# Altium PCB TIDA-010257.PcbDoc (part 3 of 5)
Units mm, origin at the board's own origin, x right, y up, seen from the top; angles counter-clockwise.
Board outline 250 x 270 mm, 2 copper layers (Top Layer, Bottom Layer), stack 1.575 mm thick; 458 components, 220 nets, 1154 pads, 1226 vias.
Unrouted connection lines stored in the file: 314.
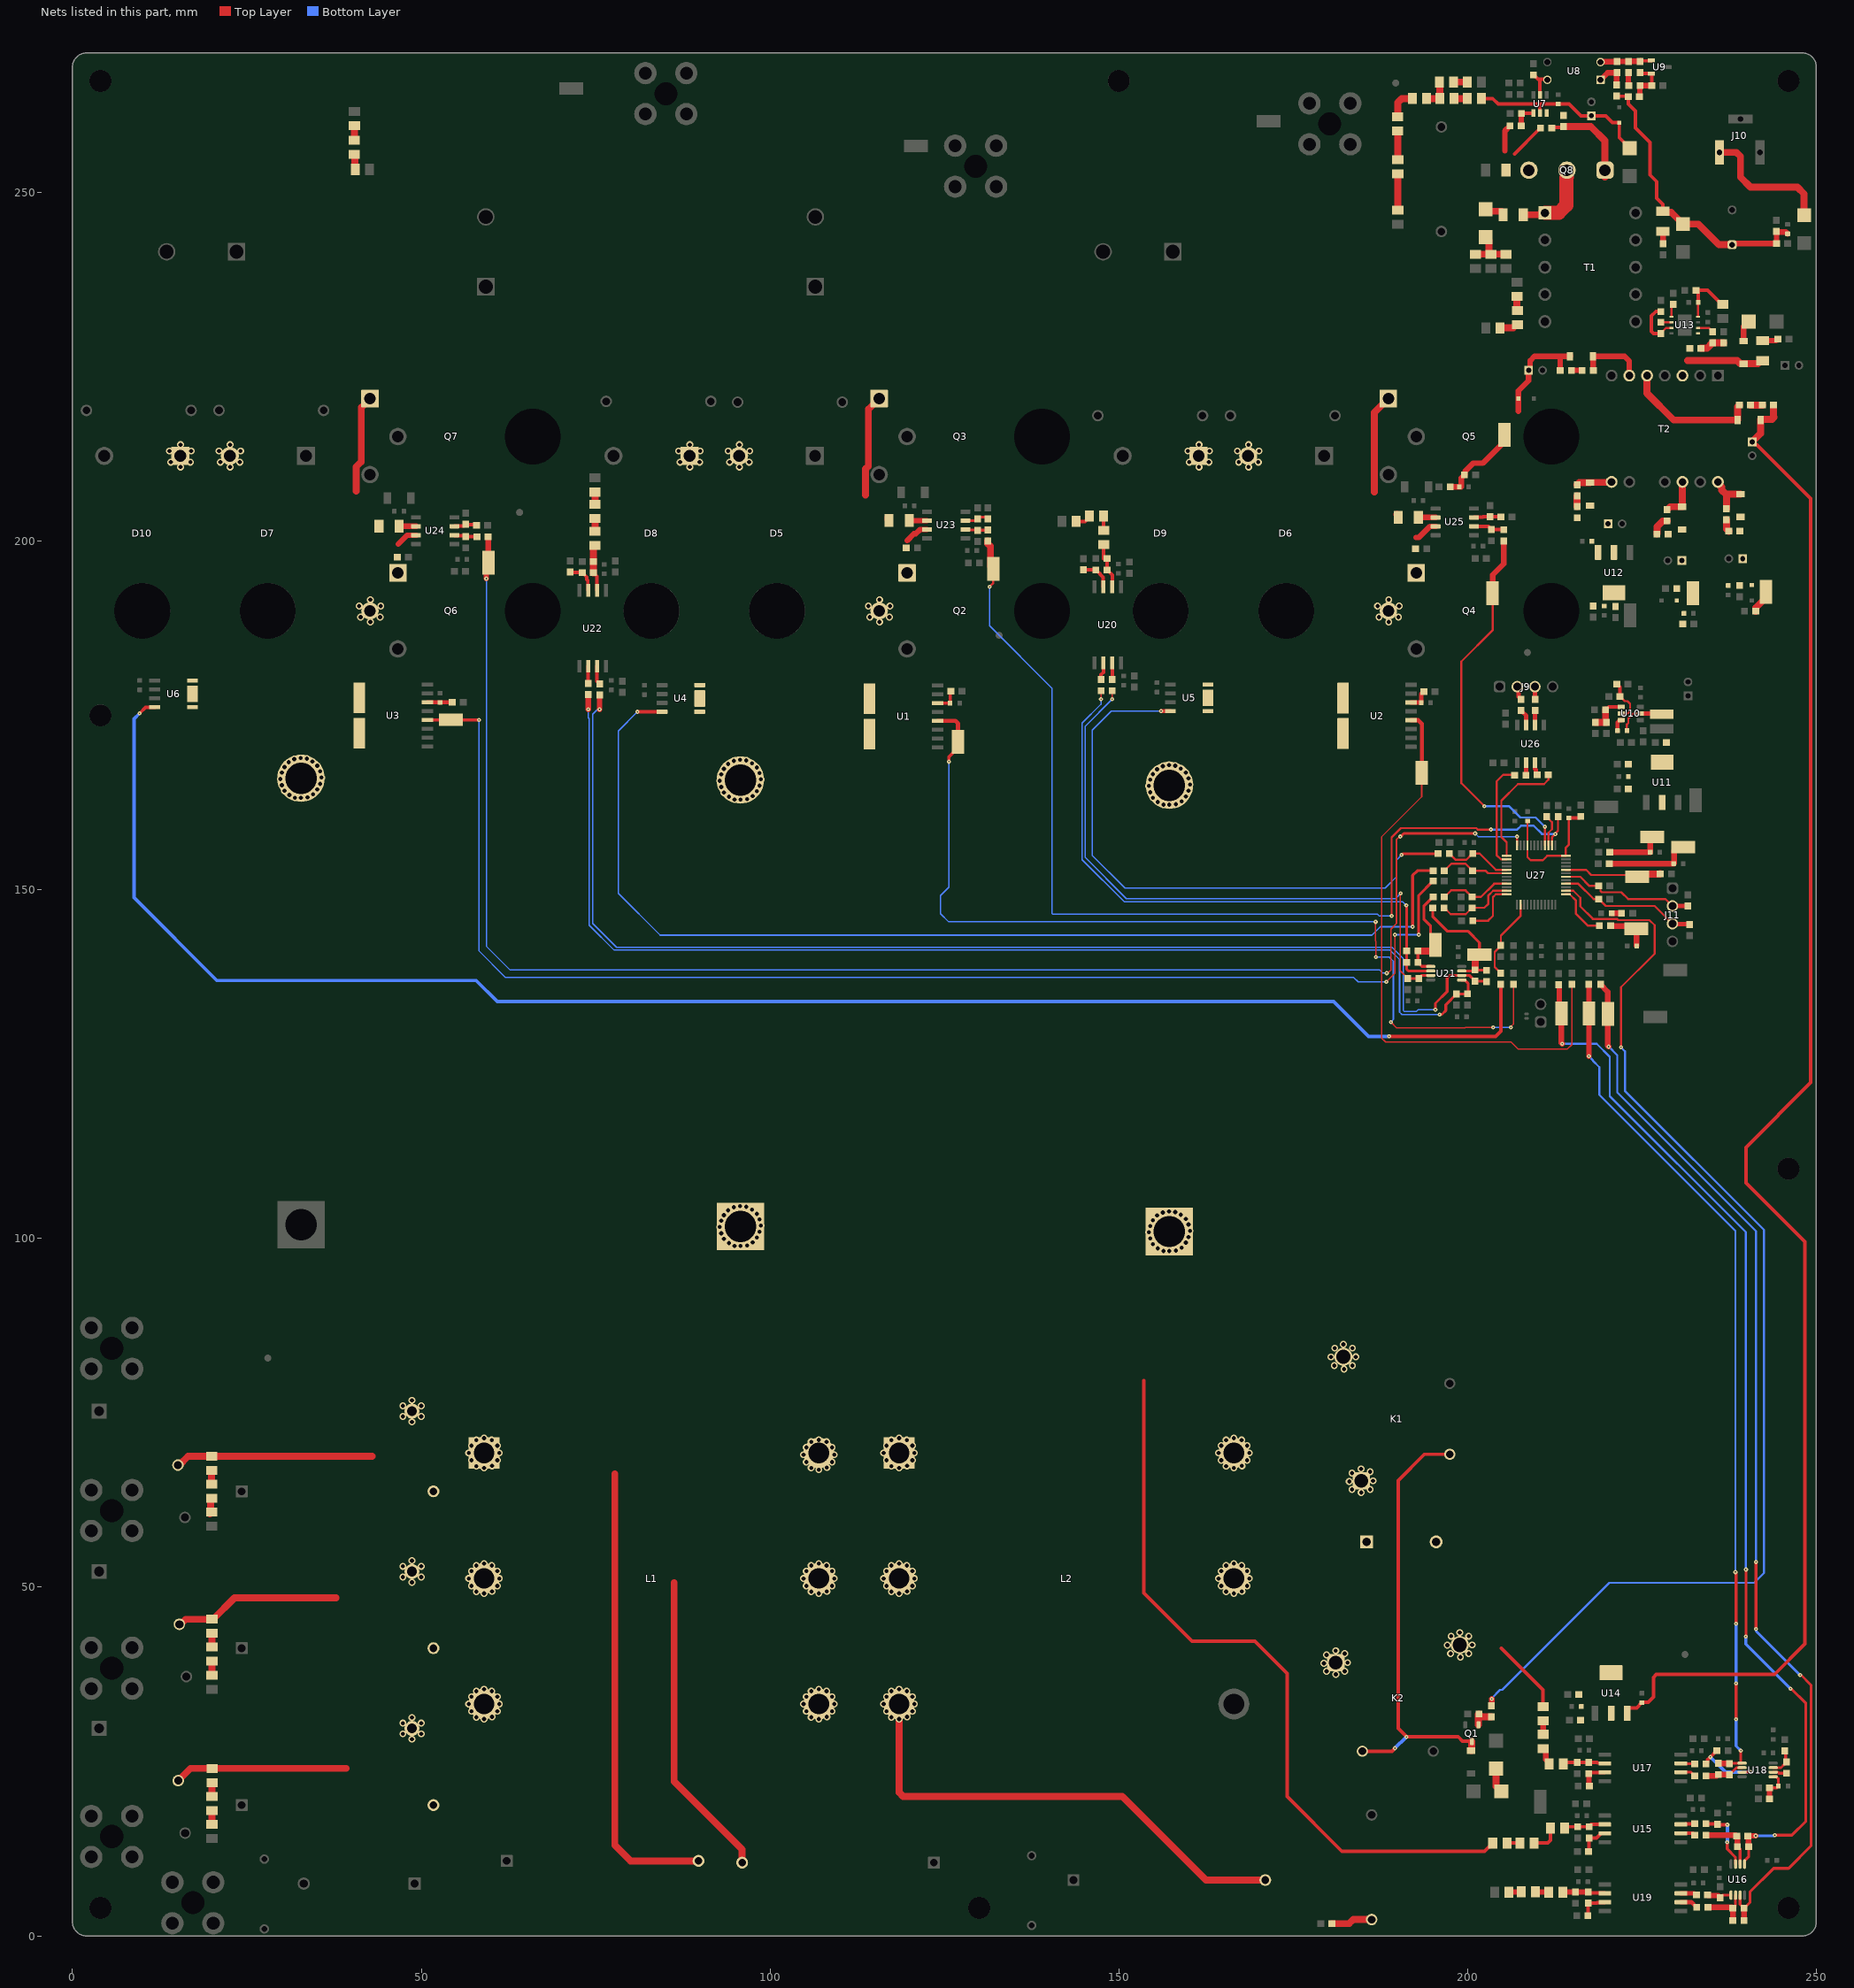
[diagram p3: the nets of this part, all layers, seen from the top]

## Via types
v1: diameter 1, hole 0.6, Top Layer to Bottom Layer, 760 vias
v2: diameter 0.6, hole 0.2, Top Layer to Bottom Layer, 452 vias
v3: diameter 1.27, hole 0.711, Top Layer to Bottom Layer, 10 vias
v4: diameter 0.5, hole 0.2, Top Layer to Bottom Layer, 4 vias

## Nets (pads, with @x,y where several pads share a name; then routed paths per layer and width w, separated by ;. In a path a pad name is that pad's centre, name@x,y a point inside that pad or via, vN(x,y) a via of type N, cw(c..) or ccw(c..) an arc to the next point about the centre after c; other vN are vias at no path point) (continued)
MCU_TCK: C151.1 J11.3 R153.1 U27.28 | length 20.3
  Top Layer w0.3: U27.28@214.088,150.877 215.878,150.877 218.07,148.685 218.467,148.685 C151.1@218.792,148.36 ; C151.1@218.792,148.684 218.817,148.684 219.815,147.686 226.824,147.686 J11.3@229.364,145.146
  Top Layer w0.6: J11.3@229.364,145.146 229.415,145.095 231.776,145.095 R153.1@231.826,145.045
MCU_TMS: C150.1 J11.2 R152.1 U27.30 | length 19.5
  Top Layer w0.3: U27.30@214.088,151.877 216.167,151.877 217.485,150.559 C150.1@218.805,150.559 219.05,150.314 219.05,149.835 219.226,149.659 222.053,149.659 223.04,148.673 228.378,148.673 J11.2@229.364,147.686
  Top Layer w0.6: J11.2@229.364,147.686 R152.1@231.601,147.686
NetC1_2: C1.2 F3.2 L1.5 R5.2 RV2.2 | length 24.8
  Top Layer w1: RV2.2@15.15,22.25 16.916,24.016 R5.2@20,24.016 39.25,24.016
  other v1: 48.67,28.2 47.36,28.968 50,28.968 47.36,30.5 50,30.5 59,31.1 48.67,31.3 57.9,31.35 60.15,31.4 57.2,32.2 60.9,32.2 56.8,33.25 61.2,33.25 57.2,34.3 60.9,34.3 57.9,35.1 60.1,35.1 59,35.375
NetC2_2: C2.2 F2.2 L1.3 R4.2 RV3.2 | length 24
  Top Layer w1: RV3.2@15.325,44.687 15.501,44.687 16.214,45.4 R4.2@19.991,45.4 20.157,45.4 23.225,48.469 37.781,48.469
  other v1: 59,49.1 57.9,49.35 60.15,49.4 57.2,50.2 60.9,50.2 48.67,50.7 56.8,51.25 61.2,51.25 47.36,51.468 50,51.468 57.2,52.3 60.9,52.3 47.36,53 50,53 57.9,53.1 60.1,53.1 59,53.375 48.67,53.8
NetC3_2: C3.2 F1.2 L1.1 R3.2 RV1.2 | length 28.4
  Top Layer w1: RV1.2@15.117,67.5 15.293,67.5 16.543,68.75 R3.2@19.95,68.75 42.95,68.75
  other v1: 59,67.1 57.9,67.35 60.15,67.4 57.2,68.2 60.9,68.2 56.8,69.25 61.2,69.25 57.2,70.3 60.9,70.3 57.9,71.1 60.1,71.1 59,71.375 48.67,73.7 47.36,74.468 50,74.468 47.36,76 50,76 48.67,76.8
NetC4_2: C4.2 L1.4 L2.3 | length 44.2
  Top Layer w1: 86.25,50.664 86.25,22.15 96,12.4 C4.2@96,10.5
  other v1: 107,49.1 118.5,49.1 105.9,49.35 117.4,49.35 108.15,49.4 119.65,49.4 105.2,50.2 108.9,50.2 116.7,50.2 120.4,50.2 104.8,51.25 109.2,51.25 116.3,51.25 120.7,51.25 105.2,52.3 108.9,52.3 116.7,52.3 120.4,52.3 105.9,53.1 108.1,53.1 117.4,53.1 119.6,53.1 107,53.375 118.5,53.375
NetC5_2: C5.2 L1.2 L2.1 | length 66.2
  Top Layer w1: 77.75,66.25 77.75,13 80,10.75 C5.2@89.75,10.75
  other v1: 107,66.85 105.9,67.1 118.5,67.1 108.15,67.15 117.4,67.35 119.65,67.4 105.2,67.95 108.9,67.95 116.7,68.2 120.4,68.2 104.8,69 109.2,69 116.3,69.25 120.7,69.25 105.2,70.05 108.9,70.05 116.7,70.3 120.4,70.3 105.9,70.85 108.1,70.85 117.4,71.1 119.6,71.1 107,71.125 118.5,71.375
NetC6_2: C6.2 L1.6 L2.5 | length 70.4
  Top Layer w1: L2.5@118.5,33.25 118.5,20.586 119.086,20 150.5,20 162.5,8 C6.2@171,8
  other v1: 107,31.1 118.5,31.1 105.9,31.35 117.4,31.35 108.15,31.4 119.65,31.4 105.2,32.2 108.9,32.2 116.7,32.2 120.4,32.2 104.8,33.25 109.2,33.25 116.3,33.25 120.7,33.25 105.2,34.3 108.9,34.3 116.7,34.3 120.4,34.3 105.9,35.1 108.1,35.1 117.4,35.1 119.6,35.1 107,35.375 118.5,35.375
NetC10_1: C10.1 R12.1 | length 6
  Top Layer w1: R12.1@180.55,1.75 183.004,1.75 183.62,2.366 C10.1@186.25,2.366
NetC13_1: C13.1 L3.2 U1.8 | length 3.7
  Top Layer w0.4: U1.8@124.02,176.78 C13.1@125.825,176.78 125.825,178.184 126.12,178.479 L3.2@126.145,178.479
NetC20_1: C20.1 L6.2 U2.8 | length 3.2
  Top Layer w0.6: U2.8@191.899,176.862 C20.1@193.353,176.862 193.353,178.093 193.699,178.44 L6.2@193.724,178.44
NetC26_1: C26.1 L8.2 U3.8 | length 3.6
  Top Layer w0.4: L8.2@54.416,176.885 L8.2@54.436,176.905
  Top Layer w0.6: U3.8@50.875,176.905 52.618,176.905 52.658,176.865 C26.1@52.683,176.865 52.703,176.885 L8.2@54.416,176.885
NetC34_1: C34.1 R26.1 | length 1.8
  Top Layer w0.8: R26.1@227.999,244.421 228.028,244.392 228.028,242.698 C34.1@228.058,242.668
NetC35_1: C35.1 C36.2 D11.1 R25.2 R26.2 R28.2 R37.2 R45.2 | length 42.1
  Top Layer w0.5: R37.2@221.364,263.837 221.397,263.803 223.021,263.803 R45.2@223.055,263.77 223.055,262.679 224.057,261.676 224.057,259.29 226.144,257.203 226.144,252.514 227.098,251.56 227.098,249.173 227.999,248.271 R26.2@227.999,247.321
  Top Layer w0.8: C35.1@237.924,242.5 238.092,242.668 R25.2@244.294,242.668 244.289,242.673 R28.2@244.289,244.392 ; R28.2@244.284,244.421 244.289,244.417 R28.2@244.289,244.392 ; C36.2@245.885,244.075 245.639,244.321 244.359,244.321 R28.2@244.289,244.392
  Top Layer w1: R26.2@227.999,247.321 228.149,247.171 229.181,247.171 D11.1@230.872,245.48 233.074,245.48 236.053,242.5 C35.1@237.924,242.5
NetC38_2: C38.2 D12.1 R30.1 R31.1 | length 7.1
  Top Layer w1: R30.1@201.113,241.157 R31.1@203.192,241.157 ; D12.1@202.589,243.597 203.057,243.129 203.057,241.292 R31.1@203.192,241.157 ; C38.2@205.521,241.157 R31.1@203.357,241.157 R31.1@203.192,241.157
NetC39_1: C39.1 R46.1 | length 1.9
  Top Layer w0.5: C39.1@223.092,265.692 223.092,265.37 C39.1@223.135,265.328
  Top Layer w0.8: R46.1@223.05,267.207 223.05,265.734 C39.1@223.092,265.692
NetC39_2: C39.2 C42.1 R45.1 R49.2 U9.2 | length 6.6
  Top Layer w0.5: R45.1@224.655,263.77 R45.1@224.695,263.81 ; C42.1@224.75,267.207 224.876,267.08 226.295,267.08 226.395,266.98 R49.2@226.395,265.328
  Top Layer w0.8: R45.1@224.695,263.81 224.695,265.287 C39.2@224.735,265.328 R49.2@226.395,265.328
NetC40_2: C40.2 C41.1 D13.1 D14.1 R42.2 U7.5 | length 26.8
  Top Layer w0.5: R42.2@202.016,263.484 203.601,263.484 204.386,262.7 210.45,262.7 ; U7.5@210.386,261.4 210.386,262.636 210.45,262.7 ; D13.1@223.25,256.36 221.75,257.86 D14.1@221.75,260.007 220.779,260.007 219.786,261 C41.1@217.75,261 216.25,261 214.55,262.7 C40.2@213,262.7 210.45,262.7
NetC42_2: C42.2 R44.1 R46.2 U8.2 U9.1 | length 7.4
  Top Layer w0.5: C42.2@224.823,268.88 226.284,268.88 U9.1@226.334,268.93
  Top Layer w0.8: U8.2@219.06,268.706 219.097,268.743 221.364,268.743 R44.1@221.401,268.78 221.414,268.794 223.037,268.794 R46.2@223.05,268.807 C42.2@224.75,268.807 C42.2@224.823,268.88
NetC43_1: C43.1 R47.1 U7.4 | length 3.6
  Top Layer w0.5: C43.1@207.721,261.344 207.749,261.372 209.408,261.372 U7.4@209.436,261.4
  Top Layer w0.8: R47.1@207.685,259.545 207.703,259.563 207.703,261.326 C43.1@207.721,261.344
NetC45_2: C45.2 U7.2 U8.4 | length 4.5
  Top Layer w0.5: C45.2@209.46,266.853 209.46,266.828 209.685,266.603 209.71,266.603 210.09,266.223 210.45,266.223 ; U7.2@210.386,264 210.386,266.16 210.45,266.223 ; U8.4@211.44,266.166 211.382,266.223 210.45,266.223
NetC46_1: C46.1 L9.1 U10.2 | length 7.2
  Top Layer w0.3: C46.1@222.843,172.822 222.843,173.715 223.053,173.925 223.053,174.597 223.74,175.284 U10.2@224.776,175.284 ; C46.1@222.993,172.61 C46.1@222.993,172.822
  Top Layer w0.6: U10.2@224.776,175.284 227.743,175.284 L9.1@227.829,175.198
NetC46_2: C46.2 U10.6 | length 1.9
  Top Layer w0.6: C46.2@221.493,172.822 221.493,174.002 221.826,174.334 U10.6@222.026,174.334
NetC48_1: C48.1 C50.2 R51.1 R53.2 U11.2 U11.4
NetC49_1: C49.1 R54.1 R56.2 U10.4 | length 5.8
  Top Layer w0.5: R56.2@219.789,175.822 219.814,175.822 220.226,176.234 U10.4@222.026,176.234
  Top Layer w1: R54.1@218.341,174.026 219.789,174.026 C49.1@219.846,174.083 ; R56.2@219.789,175.822 219.789,174.141 C49.1@219.846,174.083 ; C49.1@219.903,174.026 C49.1@219.846,174.083
NetC53_1: C53.1 C56.2 R58.2 U12.2 U12.4
NetC54_1: C54.1 C55.2 D15.1 R59.2 U12.3
NetC57_1: C57.1 R59.1 | length 1.5
  Top Layer w1: R59.1@215.691,204.958 C57.1@215.691,206.475
NetC57_2: C57.2 D15.2 T2.8 | length 5.1
  Top Layer w1: C57.2@215.691,208.075 215.995,208.379 D15.2@217.557,208.379 ; D15.2@217.557,208.422 220.568,208.422 T2.8@220.646,208.5
NetC58_1: C58.1 R60.1 | length 2.8
  Top Layer w1: R60.1@227.147,201.032 227.186,201.071 227.186,202.088 228.004,202.907 C58.1@228.611,202.907
NetC58_2: C58.2 D16.2 T2.12 | length 5.9
  Top Layer w1: C58.2@228.611,204.507 229.036,204.933 D16.2@230.768,204.933 230.787,204.952 230.787,208.481 T2.12@230.806,208.5
NetC59_2: C59.2 C60.1 D16.1 D17.1 R60.2 R61.2 R62.2 TP10.1
NetC63_2: C63.2 R63.2 | length 2.3
  Top Layer w0.8: R63.2@242.281,228.756 244.242,228.756 244.469,228.983 C63.2@244.494,228.983
NetC64_2: C64.2 C66.1 D19.1 D21.1 R64.2 R65.2 R66.2 TP11.1 | length 3.4
  Top Layer w1: R64.2@241.3,189.941 241.3,190.423 242.806,191.929 TP11.1@242.806,192.755
NetC65_1: C65.1 R65.1 | length 1.8
  Top Layer w1: C65.1@237.127,203.065 237.127,201.753 R65.1@237.446,201.434
NetC65_2: C65.2 D19.2 T2.14 | length 6.5
  Top Layer w1: T2.14@235.886,208.5 235.886,208.311 236.44,207.758 236.44,207.327 237.025,206.742 ; C65.2@237.127,204.665 237.127,206.64 237.025,206.742 ; D19.2@239.135,206.742 237.025,206.742
NetC67_1: C67.1 R71.1 R72.2 | length 3.6
  Top Layer w1: R71.1@233.463,227.656 234.337,227.656 R72.2@235.115,228.433 236.697,228.433 C67.1@236.71,228.421
NetC68_2: C68.2 C70.1 D22.1 D23.1 R67.2 R69.2 R70.2 TP12.1 | length 28.6
  Top Layer w0.8: R67.2@197.514,207.807 C68.2@198.814,207.807 199.091,207.807 199.091,209.045 199.527,209.481 199.577,209.481 199.652,209.556 199.652,210.05 200.793,211.191 202.19,211.191 204.788,213.789 204.788,214.744 TP12.1@205.277,215.233 ; 207.297,218.625 D23.1@207.297,220.45 207.297,221.546 208.75,222.998 C70.1@208.75,224.5 208.975,224.725 208.975,225.886 209.589,226.5 213.227,226.5 ; R69.2@213.29,224.5 213.29,226.436 213.227,226.5 ; D22.1@214.631,226.71 214.688,226.653 D22.1@214.688,226.5 213.227,226.5
NetC69_1: C69.1 R69.1 | length 1.5
  Top Layer w0.8: R69.1@214.89,224.5 C69.1@216.415,224.5
NetC69_2: C69.2 D22.2 T2.6 | length 9.6
  Top Layer w0.8: C69.2@217.99,224.5 C69.2@218.015,224.5 217.989,224.526 217.989,226.474 D22.2@217.963,226.5 222.5,226.5 223.186,225.814 T2.6@223.186,223.74
NetC71_2: C71.2 R68.1 R76.2 U13.4 | length 8.6
  Top Layer w0.3: U13.4@233.04,232.183 233.045,232.183 233.045,234.232 C71.2@233.051,234.238
  Top Layer w0.5: R76.2@232.74,235.988 R76.2@232.765,235.988 ; C71.2@233.051,234.238 233.051,235.702 R76.2@232.765,235.988 ; R68.1@236.601,233.949 236.436,233.949 234.397,235.988 R76.2@232.765,235.988
NetC72_1: C72.1 U13.5 | length 1.9
  Top Layer w0.3: U13.5@229.24,232.183 229.24,233.712 C72.1@229.477,233.949
NetC73_1: C73.1 R78.1 | length 1.7
  Top Layer w1: C73.1@240.557,219.5 R78.1@242.254,219.5
NetC73_2: C73.2 D24.2 T2.5 | length 19.3
  Top Layer w1: T2.5@225.726,223.74 225.726,221.213 229.562,217.378 D24.2@238.73,217.378 238.73,219.273 C73.2@238.957,219.5
NetC74_1: C74.1 C77.2 R75.2 U14.2 U14.4
NetC75_1: C75.1 C76.2 D24.1 R78.2 U14.3 | length 222.5
  Top Layer w0.5: U14.3@222.879,31.928 222.879,32.475 223.104,32.7 224.227,32.7 224.975,33.448 C76.2@225,33.448 225.069,33.517 225.903,33.517 226.637,34.251 226.637,37.078 227.06,37.5 244.017,37.5 248.369,41.852 248.369,99.531 239.909,107.991 239.909,113.059 249.2,122.35 249.2,206.125 241.45,213.875 241.175,213.875 C75.1@240.8,214.25
  Top Layer w1: C75.1@240.8,214.25 242.005,215.456 D24.1@242.005,217.378 242.005,217.446 242.048,217.488 243.645,217.488 243.957,217.8 243.854,217.903 R78.2@243.854,219.5
NetC80_1: C80.1 R79.2 R85.2 TP14.1 U16.1 | length 151
  Top Layer w0.4: U16.1@239.712,10.292 239.712,10.755 240.287,11.33 C80.1@240.287,12.787 ; v2(239.9,42.912) 239.904,42.917 239.904,52.529 v2(239.909,52.533) ; v2(244.043,14.442) 246.505,14.442 248.5,16.437 248.5,33.342 246.397,35.445 246.392,35.44 v2(246.314,35.44)
  Top Layer w0.8: R85.2@213.088,136.396 213.163,136.321 213.163,132.555 TP14.1@213.453,132.265 213.453,128.041 v2(213.56,127.934) ; R79.2@240.182,14.334 240.192,14.344 v2(241.323,14.344) ; R79.2@240.282,14.259 240.282,14.234 240.287,14.229 C80.1@240.287,12.787
  Bottom Layer w0.3: v2(213.56,127.934) 218.517,127.934 220.392,126.059 220.392,120.427 239.909,100.91 v2(239.909,52.533)
  Bottom Layer w0.4: v2(239.9,42.912) 239.9,41.854 v2(246.314,35.44) ; v2(241.323,14.344) 243.933,14.344 244.03,14.442 v2(244.043,14.442)
NetC80_2: C80.2 R79.1 R84.2 U16.2 | length 12.2
  Top Layer w0.4: U16.2@239.062,10.292 C80.2@239.062,12.437
  Top Layer w0.5: R84.2@234.18,14.442 234.234,14.388 237.981,14.388 238.035,14.334 ; C80.2@238.881,12.618 C80.2@239.062,12.437
  Top Layer w0.8: R84.2@234.18,14.442 R79.1@238.449,14.442 ; R79.1@238.582,14.334 238.607,14.334 238.682,14.259 238.682,14.234 238.687,14.229 C80.2@238.687,12.787
NetC83_1: C83.1 R82.2 R83.2 U15.2 | length 6
  Top Layer w0.5: R82.2@213.911,15.458 214.099,15.646 R83.2@215.763,15.646 C83.1@217.426,15.646 217.426,15.671 217.736,15.981 U15.2@219.677,15.981
NetC83_2: C83.2 R86.1 U15.3 | length 4.5
  Top Layer w0.5: R86.1@217.363,12.096 217.395,12.127 C83.2@217.395,14.039 ; C83.2@217.426,14.046 218.475,14.046 219.027,14.597 219.027,14.661 219.077,14.711 U15.3@219.677,14.711
NetC89_1: C89.1 R90.2 R98.2 TP15.1 U18.1 | length 124.4
  Top Layer w0.4: R90.2@235.942,24.764 R90.2@235.953,24.753 ; C89.1@237.509,24.73 C89.1@237.543,24.696 237.61,24.763 239.347,24.763 U18.1@239.357,24.772 239.198,24.772 239.175,24.795 v2(239.175,26.541) ; v2(238.401,52.162) 238.401,52.108 238.5,52.008 v2(238.5,44.771) ; v2(238.5,31.057) v2(238.5,36.2)
  Top Layer w0.8: v2(217.391,126.15) R98.2@217.391,136.44 ; R90.2@235.939,24.738 235.96,24.717 237.496,24.717 C89.1@237.509,24.73
  Bottom Layer w0.3: v2(217.391,126.15) 217.982,125.559 217.982,125.468 218.888,124.561 218.888,120.612 238.401,101.099 v2(238.401,52.162)
  Bottom Layer w0.4: v2(238.5,31.057) 238.5,27.215 v2(239.175,26.541) ; v2(238.5,36.2) v2(238.5,44.771)
NetC89_2: C89.2 R90.1 R97.2 U18.2 | length 5.4
  Top Layer w0.4: C89.2@237.552,23.13 238.535,24.113 239.347,24.113 U18.2@239.357,24.122
  Top Layer w0.8: R97.2@234.177,22.942 R90.1@235.72,22.942 ; R90.1@235.939,23.138 235.96,23.117 237.539,23.117 C89.2@237.552,23.13
NetC92_1: C92.1 R93.2 R96.1 U17.2 | length 6.1
  Top Layer w0.5: R93.2@213.713,24.662 213.913,24.862 R96.1@215.699,24.862 C92.1@217.349,24.862 218.574,24.862 218.654,24.782 219.627,24.782 U17.2@219.677,24.732
NetC92_2: C92.2 R99.1 U17.3 | length 4.2
  Top Layer w0.5: C92.2@217.4,23.312 217.499,23.412 219.627,23.412 U17.3@219.677,23.462
  Top Layer w0.8: C92.2@217.4,23.312 217.4,21.55 R99.1@217.45,21.5
NetC94_2: C94.2 R94.1 R102.2 U18.5 | length 4.9
  Top Layer w0.4: R94.1@243.292,21.225 244.325,21.225 244.575,21.475 C94.2@244.575,21.5 244.575,22.49 244.243,22.822 U18.5@243.807,22.822
  Top Layer w0.8: R102.2@243.292,19.613 R94.1@243.292,21.225
NetC99_1: C99.1 R103.2 R109.2 TP16.1 U16.7 | length 154.3
  Top Layer w0.4: U16.7@239.062,5.842 239.062,4.506 239.61,3.958 C99.1@239.635,3.958 239.66,3.958 240.473,4.771 240.473,6.289 243.867,9.684 246.028,9.684 249.25,12.906 249.25,35.968 247.718,37.5 247.718,37.467 v2(247.669,37.418) ; v2(241.344,44.017) v2(241.344,53.627)
  Top Layer w0.8: R109.2@219.069,136.44 219.069,136.415 220.113,135.371 220.113,127.635 v2(220.238,127.511) ; R103.2@239.635,2.213 C99.1@239.635,3.958
  Bottom Layer w0.3: v2(220.238,127.511) 221.464,126.284 221.464,120.943 241.344,101.064 v2(241.344,53.627)
  Bottom Layer w0.4: v2(241.344,44.017) 241.382,43.979 241.382,43.704 v2(247.669,37.418)
NetC99_2: C99.2 R103.1 R108.2 U16.6 | length 7.4
  Top Layer w0.4: C99.2@237.973,4.02 C99.2@238.035,3.958 238.06,3.958 238.412,4.31 U16.6@238.412,5.842
  Top Layer w0.8: R108.2@234.443,4.082 237.886,4.082 237.948,4.02 C99.2@237.973,4.02 ; R103.1@238.035,2.213 C99.2@238.035,3.958
NetC102_1: C102.1 R106.2 R107.1 U19.2 | length 6.3
  Top Layer w0.5: R106.2@213.667,6.106 R106.2@213.667,6.271 ; C102.1@217.315,6.298 217.458,6.155 219.627,6.155 U19.2@219.677,6.105
  Top Layer w0.8: R106.2@213.667,6.271 213.681,6.284 217.302,6.284 C102.1@217.315,6.298
NetC102_2: C102.2 R110.1 U19.3 | length 4.2
  Top Layer w0.5: R110.1@217.252,2.921 217.283,2.953 217.283,4.666 C102.2@217.315,4.698 218.54,4.698 218.627,4.785 219.627,4.785 U19.3@219.677,4.835
NetC108_1: C108.1 R113.1 R119.1 TP17.1 U21.1 | length 15
  Top Layer w0.4: R113.1@192.882,141.218 192.88,141.215 192.88,139.588 C108.1@192.878,139.586 192.903,139.586 193.21,139.279 193.21,139.254 193.444,139.019 U21.1@194.715,139.019 ; R119.1@195.079,148.995 195.054,148.995 193.724,147.665 193.724,145.793 194.702,144.816 194.702,142.792 TP17.1@195.391,142.103
  Top Layer w1: R113.1@192.882,141.218 195.002,141.218 195.391,141.607 TP17.1@195.391,142.103
NetC108_2: C108.2 R113.2 R118.2 U21.2 | length 87.3
  Top Layer w0.2: v2(147.439,177.335) R118.2@147.439,178.543
  Top Layer w0.4: v2(191.214,147.767) 191.214,147.713 191.282,147.645 R113.2@191.282,141.218 191.278,141.213 C108.2@191.278,139.586 191.278,138.603 191.512,138.369 U21.2@194.715,138.369
  Bottom Layer w0.2: v2(147.439,177.335) 147.439,176.607 144.75,173.918 144.75,154.306 150.749,148.307 190.674,148.307 v2(191.214,147.767)
NetC111_1: C111.1 R116.2 R117.1 U20.2 | length 6.3
  Top Layer w0.5: R117.1@147.8,197.506 R116.2@147.8,199.392 ; R116.2@147.821,199.335 R116.2@147.871,199.385 ; R117.1@148.3,197.506 C111.1@148.3,195.868 148.325,195.868 149.058,195.135 U20.2@149.058,193.45
NetC111_2: C111.2 R120.1 U20.3 | length 4.6
  Top Layer w0.5: R120.1@144.948,195.876 144.952,195.872 146.696,195.872 C111.2@146.7,195.868 146.725,195.868 147.288,195.305 147.288,195.269 147.738,194.819 147.738,193.5 U20.3@147.788,193.45
NetC117_1: C117.1 R124.1 R130.1 TP18.1 U21.7 | length 17.5
  Top Layer w0.2: C117.1@201.017,138.444 C117.1@201.092,138.519 ; R124.1@202.655,138.519 R124.1@202.719,138.456
  Top Layer w0.4: R130.1@195.031,147.428 195.031,146.121 197.06,144.093 200.035,144.093 201.704,142.423 TP18.1@201.704,140.729 ; U21.7@199.165,138.369 199.175,138.379 200.952,138.379 C117.1@201.017,138.444 ; C117.1@201.092,138.519 201.124,138.487 202.624,138.487 R124.1@202.655,138.519
  Top Layer w1: C117.1@201.092,138.519 201.092,140.34 201.481,140.729 TP18.1@201.704,140.729
NetC117_2: C117.2 R124.2 R129.2 U21.6 | length 175.3
  Top Layer w0.2: C117.2@201.092,136.919 C117.2@201.092,136.944 ; R124.2@202.655,136.919 R124.2@202.719,136.856
  Top Layer w0.4: v2(195.39,132.814) 195.39,133.724 197.063,135.397 197.063,137.361 197.422,137.719 U21.6@199.165,137.719 200.317,137.719 C117.2@201.092,136.944 ; C117.2@201.092,136.919 201.124,136.887 202.624,136.887 R124.2@202.655,136.919
  Top Layer w0.8: v2(75.565,175.882) R129.2@75.565,177.95
  Bottom Layer w0.2: v2(75.565,175.882) 75.259,175.882 74.565,175.188 74.565,145.185 78,141.75 189.162,141.75 190.809,140.103 190.809,132.665 190.926,132.548 192.651,132.548 192.917,132.814 v2(195.39,132.814)
NetC120_1: C120.1 R127.2 R128.2 U22.2 | length 6.8
  Top Layer w0.5: C120.1@74.674,195.475 74.699,195.475 75.2,194.975 U22.2@75.2,192.95
  Top Layer w1: C120.1@74.674,195.475 R128.2@74.674,197.057 74.674,199.242 74.809,199.377 R127.2@74.915,199.377
NetC120_2: C120.2 R131.2 U22.3 | length 4.7
  Top Layer w0.5: R131.2@71.315,195.567 71.361,195.521 73.028,195.521 C120.2@73.074,195.475 73.099,195.475 73.724,194.85 73.724,194.512 73.88,194.356 73.88,193 U22.3@73.93,192.95
NetC125_1: C125.1 R135.1 U23.2 | length 3.3
  Top Layer w0.4: U23.2@128.001,201.677 128.064,201.613 129.687,201.613 C125.1@129.75,201.55 129.782,201.582 131.181,201.582 R135.1@131.213,201.613
NetC128_1: C128.1 R137.1 U23.3 | length 3.4
  Top Layer w0.4: U23.3@128.001,202.947 129.305,202.947 129.75,203.392 129.75,203.417 129.763,203.43 131.2,203.43 R137.1@131.213,203.444
NetC133_1: C133.1 R138.1 U24.2 | length 3.3
  Top Layer w0.5: U24.2@54.75,200.858 54.8,200.808 56.208,200.808 C133.1@56.374,200.643 R138.1@57.979,200.643
NetC136_1: C136.1 R140.1 U25.2 | length 4.6
  Top Layer w0.5: U25.2@200.922,202.127 202.991,202.127 203.436,201.682 C136.1@203.436,201.657 203.446,201.647 205.165,201.647 R140.1@205.175,201.637 R140.1@205.245,201.567
NetC139_1: C139.1 R142.1 U24.3 | length 3
  Top Layer w0.5: U24.3@54.75,202.128 54.8,202.178 C139.1@56.113,202.178 ; C139.1@56.35,202.44 56.424,202.366 57.855,202.366 R142.1@57.929,202.293
NetC140_1: C140.1 R143.1 U25.3 | length 3.9
  Top Layer w0.5: U25.3@200.922,203.397 200.972,203.447 202.165,203.447 202.211,203.492 C140.1@203.209,203.492 ; C140.1@203.209,203.503 203.227,203.484 204.749,203.484 R143.1@204.768,203.465
NetC143_2: C143.2 R144.2 TP22.1 | length 12.6
  Top Layer w0.8: R144.2@220.341,153.752 229.537,153.752 C143.2@229.551,153.766 229.595,153.81 229.595,155.605 230.084,156.094 TP22.1@230.909,156.094
NetC144_2: C144.2 R145.2 TP23.1 | length 9.2
  Top Layer w0.3: TP23.1@226.19,157.635 TP23.1@226.19,158.316 ; TP23.1@227.15,157.626 TP23.1@227.679,157.626
  Top Layer w0.8: R145.2@220.405,155.402 C144.2@226.19,155.402 TP23.1@226.19,157.635
NetC146_1: C146.1 C147.2 C148.1 U27.36 U27.45 | length 18.6
  Top Layer w0.3: C146.1@208.588,159.877 U27.45@208.588,156.377 208.588,154.694 209.031,154.252 210.802,154.252 211.427,154.877 U27.36@214.088,154.877 214.088,156.057 214.532,156.502 C148.1@214.532,160.313
  Top Layer w0.5: C148.1@214.532,160.313 216.023,160.313 C147.2@216.248,160.538
NetC156_1: C156.1 U27.12 | length 8
  Top Layer w0.3: C156.1@200.753,145.578 202.954,145.578 203.637,146.261 203.637,148.968 204.046,149.377 U27.12@205.588,149.377
NetC157_2: C157.2 R158.2 TP27.1 | length 6.4
  Top Layer w0.8: R158.2@220.488,144.885 220.563,144.81 223.823,144.81 TP27.1@224.212,144.421 224.236,144.397 C157.2@224.236,141.967
NetD1_2: D1.2 J10.1 | length 19.4
  Top Layer w1: J10.1@236.124,255.75 238.538,255.75 239.124,255.164 239.124,252.2 240.567,250.757 247.273,250.757 248.25,249.78 D1.2@248.25,246.75
NetD3_1: D3.1 D4.2 | length 3.6
  Top Layer w1: D3.1@204.086,24 204.086,21.475 D4.2@204.831,20.729
NetD12_2: D12.2 R34.1 | length 3.1
  Top Layer w1: D12.2@202.592,247.808 203.092,247.308 204.861,247.308 205.087,247.082 R34.1@205.087,246.807
NetD18_1: D18.1 D20.1 | length 2.8
  Top Layer w0.8: D20.1@239.581,228.698 239.581,230.782 D18.1@240.087,231.288
NetD20_2: D20.2 R63.1 R71.2 T2.3 U13.1 | length 11.1
  Top Layer w1: 231.526,225.912 238.649,225.912 239.095,225.466 241.615,225.466 242.006,225.856 R63.1@242.281,225.856
NetD25_1: D25.1 R156.2 | length 1.4
  Top Layer w0.8: D25.1@220.658,146.628 R156.2@222.072,146.628
NetK1_1: K1.1 L2.2
  other v1: 184.75,63.571 183.431,64.002 186.031,64.002 183.04,65.171 186.44,65.257 183.431,66.37 186.031,66.542 184.74,66.971 166.5,67.1 165.4,67.35 167.65,67.4 164.7,68.2 168.4,68.2 164.3,69.25 168.7,69.25 164.7,70.3 168.4,70.3 165.4,71.1 167.6,71.1 166.5,71.375
NetK2_1: K2.1 L2.4 RT1.1
  other v1: 181.11,37.5 179.791,37.931 182.391,37.931 179.4,39.1 182.8,39.186 179.791,40.299 182.391,40.471 181.1,40.9 166.5,49.1 165.4,49.35 167.65,49.4 164.7,50.2 168.4,50.2 164.3,51.25 168.7,51.25 164.7,52.3 168.4,52.3 165.4,53.1 167.6,53.1 166.5,53.375
NetL4_2: L4.2 U1.2
  other v1: 94.9,162.95 95.75,162.95 96.7,163.015 94.1,163.35 97.5,163.45 93.4,163.95 98.1,164.15 93,164.75 98.5,164.95 92.8,165.65 98.7,165.85 93,166.55 98.5,166.75 93.4,167.35 98.1,167.55 94,168.05 97.4,168.15 94.8,168.485 96.6,168.55 95.7,168.65
NetL7_2: L7.2 U3.2
  other v1: 31.9,163.2 32.75,163.2 33.7,163.265 31.1,163.6 34.5,163.7 30.4,164.2 35.1,164.4 30,165 35.5,165.2 29.8,165.9 35.7,166.1 30,166.8 35.5,167 30.4,167.6 35.1,167.8 31,168.3 34.4,168.4 31.8,168.735 33.6,168.8 32.7,168.9
NetQ1_1: Q1.1 R1.1 R2.1 | length 3.5
  Top Layer w1: Q1.1@201.562,30.26 201.562,31.733 R2.1@201.638,31.809 202.044,31.403 R1.1@203.395,31.403
NetQ8_1: Q8.1 R40.2 R43.2 | length 13.8
  Top Layer w0.5: R43.2@212.05,259.25 212.146,259.346 213.654,259.346 R40.2@213.75,259.443
  Top Layer w1: R40.2@213.75,259.443 217.675,259.443 219.7,257.418 Q8.1@219.7,252.204
NetQ8_2: Q8.2 R34.2 T1.1 | length 10.8
  Top Layer w1: R34.2@207.987,246.807 210.825,246.807 T1.1@211.098,247.08
  Top Layer w2: T1.1@211.098,247.08 213.078,247.08 214.154,248.156 214.154,252.109 Q8.2@214.25,252.204
NetQ8_3: Q8.3 R43.1 R47.2 R48.2 | length 9.2
  Top Layer w0.5: 206.718,255.518 210.2,259 210.2,259.025 210.425,259.25 R43.1@210.45,259.25 ; Q8.3@208.8,252.204 Q8.3@208.8,252.264
  Top Layer w0.8: 205.345,255.993 205.345,258.831 206.06,259.545 R47.2@206.085,259.545
NetR3_1: R3.1 R6.2 | length 2
  Top Layer w1: R6.2@19.95,64.75 R3.1@19.95,66.718
NetR4_1: R4.1 R7.2 | length 2
  Top Layer w1: R7.2@19.991,41.416 R4.1@19.991,43.368
NetR5_1: R5.1 R8.2 | length 2
  Top Layer w1: R8.2@19.991,20.016 19.996,20.02 19.996,21.98 R5.1@20,21.984
NetR6_1: R6.1 R9.2 | length 2.3
  Top Layer w1: R9.2@19.7,60.5 19.825,60.625 19.825,62.593 R6.1@19.95,62.718
NetR7_1: R7.1 R10.2 | length 2
  Top Layer w1: R10.2@19.991,37.4 R7.1@19.991,39.384
NetR8_1: R8.1 R11.2 | length 2
  Top Layer w1: R11.2@19.991,16.016 R8.1@19.991,17.984
NetR13_2: R13.2 TP1.1 U1.6 | length 134.9
  Top Layer w0.2: v2(186.813,145.416) 186.813,142.636 186.859,142.591 v2(186.859,140.354) ; v2(189,131.043) 189.851,130.192 199.625,130.192 199.717,130.284 v2(203.685,130.284) ; v2(206.213,130.284) 206.213,130.392 206.563,130.742 206.563,136.425 R13.2@206.578,136.44
  Top Layer w0.5: v2(125.645,168.373) 125.645,169.08 126.952,170.386 TP1.1@126.952,171.212
  Top Layer w0.6: U1.6@124.02,174.24 126.575,174.24 126.952,173.863 TP1.1@126.952,171.212
  Bottom Layer w0.2: v2(125.645,168.373) 125.645,150.395 124.428,149.178 124.428,146.587 125.599,145.416 v2(186.813,145.416) ; v2(186.859,140.354) 186.872,140.368 188.749,140.368 189.36,139.757 189.36,131.404 v2(189,131.043) ; v2(203.685,130.284) v2(206.213,130.284)
NetR14_1: R14.1 R16.2 | length 2
  Top Layer w1: R16.2@207.073,233.092 R14.1@207.073,235.105
NetR15_2: R15.2 TP3.1 U2.6 | length 86.3
  Top Layer w0.2: TP3.1@193.724,167.09 TP3.1@193.421,166.787 193.421,163.346 187.659,157.583 187.659,128.761 188.253,128.167 206.229,128.167 207.213,127.183 214.336,127.183 214.963,127.81 R15.2@214.963,136.44
  Top Layer w0.6: U2.6@191.899,174.322 192.954,174.322 193.458,173.818 193.458,167.357 TP3.1@193.724,167.09
NetR16_1: R16.1 R17.2 | length 2.7
  Top Layer w1: R17.2@204.654,230.583 206.532,230.583 206.925,230.976 R16.1@207.184,230.976
NetR18_2: R18.2 TP5.1 U3.6 | length 191.7
  Top Layer w0.2: v2(188.36,136.792) 189.6,138.032 v2(189.6,143.565)
  Top Layer w0.4: v2(192.998,143.565) 192.998,149.206 195.043,151.252 R18.2@195.068,151.252
  Top Layer w0.5: U3.6@50.875,174.365 v2(58.284,174.365)
  Bottom Layer w0.2: v2(58.284,174.365) 58.284,171.918 58.25,171.884 58.25,141.268 62.094,137.424 183.673,137.424 184.305,136.792 v2(188.36,136.792) ; v2(189.6,143.565) v2(192.998,143.565)
NetR19_1: R19.1 R20.2 | length 2.2
  Top Layer w1: R20.2@40.37,255.468 40.461,255.377 40.461,253.635 R19.1@40.553,253.544 ; R19.1@40.514,253.3 R19.1@40.514,253.465
NetR20_1: R20.1 R21.2 | length 2
  Top Layer w1: R20.1@40.411,257.567 R21.2@40.411,259.584
NetR22_2: R22.2 U4.4 | length 158.1
  Top Layer w0.4: v2(192.125,144.709) 192.125,152.078 192.8,152.752 R22.2@195.068,152.752
  Top Layer w0.5: v2(80.996,175.522) 81.01,175.536 U4.4@84.525,175.536
  Bottom Layer w0.2: v2(80.996,175.522) 78.25,172.776 78.25,149.5 84.25,143.5 186.282,143.5 187.492,144.709 v2(192.125,144.709)
NetR23_2: R23.2 U5.4 | length 85.3
  Top Layer w0.4: v2(190.554,155.002) 190.608,155.002 190.79,155.184 R23.2@195.792,155.184
  Top Layer w0.6: v2(156.065,175.625) U5.4@157.4,175.625
  Bottom Layer w0.2: v2(156.065,175.625) 148.912,175.625 146.2,172.913 146.2,154.921 150.878,150.243 188.186,150.243 189.806,151.863 189.806,154.253 v2(190.554,155.002)
NetR24_2: R24.2 U6.4 | length 240.5
  Top Layer w0.5: v2(9.618,175.311) 10.495,176.188 U6.4@11.784,176.188 ; v2(188.749,129) 204.038,129 204.772,129.734 R24.2@204.772,136.44
  Bottom Layer w0.5: v2(9.618,175.311) 8.815,174.508 8.815,148.885 20.7,137 57.883,137 60.883,134 180.786,134 185.786,129 v2(188.749,129)
NetR27_1: R27.1 R29.2 | length 5.2
  Top Layer w1: R27.1@190,247.497 R29.2@190,252.688
NetR29_1: R29.1 R32.2 | length 4.1
  Top Layer w1: R32.2@189.983,258.853 189.991,258.844 189.991,254.729 R29.1@190,254.72
NetR32_1: R32.1 R33.2 | length 4.3
  Top Layer w1: R32.1@189.983,260.885 189.983,262.881 190.568,263.466 R33.2@192.084,263.466
NetR33_1: R33.1 R36.2 R41.1 | length 4.3
  Top Layer w1: R33.1@194.116,263.466 194.118,263.468 195.982,263.468 196.017,263.503 196.017,265.805 R36.2@195.984,265.839
NetR35_2: R35.2 R36.1 | length 2
  Top Layer w1: R36.1@198.016,265.839 R35.2@199.984,265.839
NetR37_1: R37.1 R44.2 U8.1 | length 4.5
  Top Layer w0.8: U8.1@219.06,266.166 220.075,267.18 R44.2@221.401,267.18 221.382,267.162 221.382,265.455 R37.1@221.364,265.437
NetR40_1: R40.1 U7.6
NetR41_2: R41.2 R42.1 | length 1.9
  Top Layer w1: R41.2@198.083,263.47 198.09,263.477 199.977,263.477 R42.1@199.984,263.484
NetR52_1: R52.1 R55.2 U10.5 | length 6.4
  Top Layer w0.3: R55.2@221.837,177.75 221.862,177.75 222.553,177.059 222.936,177.059 223.3,176.695 223.3,175.623 222.962,175.284 U10.5@222.026,175.284
  Top Layer w0.5: R52.1@221.397,179.526 221.422,179.526 221.837,179.111 R55.2@221.837,177.75
NetR72_1: R72.1 U13.2 | length 2.3
  Top Layer w0.3: U13.2@233.04,230.583 234.59,230.583 235.102,230.071 R72.1@235.102,230.046
NetR73_1: R73.1 R77.2 U13.7 | length 7.2
  Top Layer w0.3: R73.1@227.69,229.783 227.69,229.808 228.465,230.583 U13.7@229.24,230.583
  Top Layer w0.5: R73.1@227.69,229.783 226.641,229.783 226.348,230.076 226.348,232.304 227.011,232.967 227.637,232.967 R77.2@227.69,232.914
NetR73_2: R73.2 U13.6 | length 1.6
  Top Layer w0.3: R73.2@227.69,231.383 U13.6@229.24,231.383
NetR80_2: R80.2 R81.1 | length 1.9
  Top Layer w0.5: R80.2@205.638,13.322 R81.1@207.519,13.322
NetR81_2: R81.2 R82.1 | length 4.2
  Top Layer w0.5: R81.2@209.551,13.322 211.509,13.322 211.879,13.692 R82.1@211.879,15.458
NetR84_1: R84.1 U15.6 | length 2.1
  Top Layer w0.5: U15.6@230.577,14.711 232.286,14.711 232.555,14.442 R84.1@232.58,14.442
NetR87_1: R87.1 U15.7 | length 2
  Top Layer w0.5: U15.7@230.577,15.981 231.177,15.981 231.261,16.065 R87.1@232.58,16.065
NetR87_2: R87.2 R88.2 U16.3 | length 9.4
  Top Layer w0.4: v2(237.219,13.416) 237.219,12.461 238.403,11.277 238.403,10.765 238.412,10.755 U16.3@238.412,10.292
  Top Layer w0.5: R87.2@234.18,16.065 234.206,16.039 235.805,16.039 R88.2@235.831,16.013 235.894,15.949 237.289,15.949 237.284,15.944 v2(237.245,15.944)
  Bottom Layer w0.5: v2(237.219,13.416) 237.212,13.416 237.187,13.441 237.245,13.498 v2(237.245,15.944)
NetR89_1: R89.1 R95.1 U18.7 | length 4
  Top Layer w0.4: U18.7@243.807,24.122 244.929,24.122 R89.1@245.479,24.672
  Top Layer w0.5: R89.1@245.479,24.672 245.704,24.897 R89.1@245.704,24.922 245.602,25.025 245.602,26.443 R95.1@245.5,26.545
NetR89_2: R89.2 U18.6 | length 2
  Top Layer w0.4: U18.6@243.807,23.472 243.816,23.463 244.5,23.463 244.64,23.322 R89.2@245.704,23.322
NetR91_2: R91.2 R92.1 | length 1.9
  Top Layer w0.8: R92.1@210.818,28.905 R91.2@210.818,30.844
NetR92_2: R92.2 R93.1 | length 2.7
  Top Layer w0.8: R92.2@210.818,26.873 210.983,26.873 211.218,26.638 211.218,25.291 211.681,24.827 R93.1@211.681,24.662
NetR97_1: R97.1 U17.6 | length 2.2
  Top Layer w0.4: U17.6@230.577,23.462 232.043,23.462 232.277,23.228 232.277,23.217 232.552,22.942 R97.1@232.577,22.942
NetR100_1: R100.1 U17.7 | length 2
  Top Layer w0.4: U17.7@230.577,24.732 230.612,24.697 232.542,24.697 R100.1@232.577,24.662
NetR100_2: R100.2 R101.2 U18.3 | length 10.5
  Top Layer w0.4: U18.3@239.357,23.472 v2@240.359,23.472
  Top Layer w0.5: R100.2@234.177,24.662 234.202,24.662 234.427,24.887 234.427,25.261 v2(234.812,25.646) 235.732,26.566 R101.2@235.757,26.566 ; v2@240.359,23.472 240.387,23.5 v2(240.558,23.5)
  Bottom Layer w0.5: v2(234.812,25.646) 236.985,23.472 240.586,23.472 v2(240.558,23.5)
NetR104_2: R104.2 R105.1 | length 1.8
  Top Layer w0.8: R104.2@205.923,6.271 205.936,6.284 207.699,6.284 R105.1@207.712,6.298
NetR105_2: R105.2 R106.1 | length 1.9
  Top Layer w0.8: R105.2@209.744,6.298 209.758,6.284 211.622,6.284 R106.1@211.635,6.271
NetR108_1: R108.1 U19.6 | length 2.6
  Top Layer w0.4: R108.1@232.818,4.082 R108.1@232.843,4.082
  Top Layer w0.6: U19.6@230.577,4.835 232.065,4.835 R108.1@232.818,4.082
NetR111_1: R111.1 U19.7 | length 2.3
  Top Layer w0.6: U19.7@230.577,6.105 232.542,6.105 232.79,5.857 R111.1@232.815,5.857
NetR111_2: R111.2 R112.2 U16.5 | length 3.7
  Top Layer w0.4: R112.2@236.182,5.496 236.528,5.842 U16.5@237.762,5.842
  Top Layer w0.8: R111.2@234.415,5.857 234.49,5.782 235.896,5.782 236.182,5.496 R112.2@236.182,5.471
NetR114_2: R114.2 R115.1 | length 2.3
  Top Layer w0.5: R114.2@143.907,202.837 145.167,202.837 145.772,203.442 R115.1@145.772,203.607
NetR115_2: R115.2 R116.1 | length 2
  Top Layer w0.5: R115.2@147.804,203.607 147.804,201.59 R116.1@147.825,201.569
NetR118_1: R118.1 U20.6 | length 2.6
  Top Layer w0.5: R118.1@147.44,180.144 147.44,180.866 147.724,181.151 147.788,181.151 U20.6@147.788,182.55
NetR121_1: R121.1 U20.7 | length 2.4
  Top Layer w0.5: R121.1@149.058,180.143 U20.7@149.058,182.55
NetR121_2: R121.2 R122.1 R123.1 U21.3 | length 89.7
  Top Layer w0.2: R121.2@149.058,178.543 v2(149.058,177.335) 149.058,177.24 v2@149.065,177.233 ; v2(190.427,149.502) 190.363,149.437 190.363,138.401 191.444,137.319 R122.1@191.444,137.294
  Top Layer w0.4: R122.1@191.444,137.294 R123.1@192.998,137.294 192.998,137.319 193.398,137.719 U21.3@194.715,137.719
  Bottom Layer w0.2: v2(149.058,177.335) 145.2,173.477 145.2,154.633 151.083,148.75 189.675,148.75 v2(190.427,149.502)
NetR125_2: R125.2 R126.1 | length 1.8
  Top Layer w1: R126.1@74.915,205.272 R125.2@74.915,207.031
NetR126_2: R126.2 R127.1 | length 1.8
  Top Layer w1: R127.1@74.915,201.409 R126.2@74.915,203.24
NetR129_1: R129.1 U22.7 | length 2.7
  Top Layer w0.5: U22.7@75.2,182.05 75.2,179.94 75.565,179.575 R129.1@75.565,179.55
NetR132_1: R132.1 U22.6 | length 2.4
  Top Layer w0.5: R132.1@73.93,179.6 U22.6@73.93,182.05
NetR132_2: R132.2 R133.1 R134.1 U21.5 | length 173.1
  Top Layer w0.4: v2(195.99,132.112) 196.028,132.15 196.336,132.15 196.889,132.704 196.889,133.531 198.432,135.073 199.963,135.073 R133.1@199.979,135.089 200.067,135.177 200.067,136.604 199.602,137.069 U21.5@199.165,137.069
  Top Layer w0.8: v2(73.93,175.882) R132.2@73.93,178
  Bottom Layer w0.2: v2(73.93,175.882) 73.93,174.695 74.065,174.56 74.065,144.935 77.65,141.35 188.901,141.35 190.25,140.001 190.25,132.448 190.586,132.112 v2(195.99,132.112)
NetR136_1: R136.1 U23.6 | length 2.5
  Top Layer w0.8: R136.1@119.954,202.947 U23.6@122.501,202.947
NetR139_1: R139.1 U24.6 | length 2.4
  Top Layer w0.8: R139.1@46.825,202.128 U24.6@49.25,202.128
NetR141_1: R141.1 U25.6 | length 2.5
  Top Layer w0.8: R141.1@192.954,203.397 U25.6@195.422,203.397
NetR146_2: R146.2 U26.2 | length 2.1
  Top Layer w0.3: R146.2@208.163,166.25 R146.2@208.397,166.484
  Top Layer w0.6: R146.2@208.397,166.484 U26.2@208.397,168.237
NetR147_1: R147.1 U26.7 | length 2.4
  Top Layer w0.6: R147.1@207.663,175.714 207.663,175.689 207.838,175.514 207.863,175.514 208.397,174.98 U26.7@208.397,173.637
NetR148_1: R148.1 U26.6 | length 2.1
  Top Layer w0.6: U26.6@209.667,173.637 209.667,175.69 R148.1@209.691,175.714
NetR149_2: R149.2 U26.3 | length 2
  Top Layer w0.3: R149.2@209.667,166.296 R149.2@209.713,166.25
  Top Layer w0.6: U26.3@209.667,168.237 209.667,167.33 209.779,167.218 209.779,166.654 209.954,166.479 R149.2@209.979,166.479
NetR151_1: R151.1 U27.39 | length 4.6
  Top Layer w0.3: R151.1@211.348,160.478 211.348,160.453 212.107,159.693 212.107,158.7 211.588,158.181 U27.39@211.588,156.377
NetR157_1: R157.1 TP26.1 U27.32 | length 14.1
  Top Layer w0.3: U27.32@214.088,152.877 216.982,152.877 217.725,152.134 224.081,152.134 TP26.1@224.339,151.877
  Top Layer w1: TP26.1@224.339,151.877 224.728,152.266 227.553,152.266 227.584,152.297 R157.1@227.639,152.297
NetR158_1: R158.1 U27.25 | length 7.8
  Top Layer w0.3: U27.25@214.088,149.377 214.638,149.377 215.55,148.465 215.55,146.548 217.212,144.885 R158.1@218.888,144.885
PWMA: R135.2 R155.2 TP19.1 U27.38 | length 147.1
  Top Layer w0.3: v2(131.463,193.45) 132,193.987 TP19.1@132,196.03 ; v2(189.117,146.243) 189.117,157.514 190.457,158.854 201.247,158.854 201.453,158.648 v2(203.355,158.648) ; U27.38@212.088,156.377 212.088,157.527 212.572,158.011 v2(212.578,158.011) 212.578,158.092 212.965,158.48 R155.2@212.965,160.478
  Top Layer w1: R135.2@131.213,200.013 131.213,199.642 131.611,199.244 131.611,196.419 TP19.1@132,196.03
  Bottom Layer w0.2: v2(131.463,193.45) 131.463,187.873 140.4,178.936 140.4,146.618 140.518,146.501 187.088,146.501 187.346,146.243 v2(189.117,146.243)
  Bottom Layer w0.3: v2(203.355,158.648) 207.122,158.648 207.682,159.208 209.466,159.208 210.663,158.011 v2(212.578,158.011)
PWMB: R140.2 TP21.1 U27.40 | length 54.3
  Top Layer w0.3: v2(202.406,162.007) 199.107,165.307 199.107,182.741 203.593,187.227 TP21.1@203.593,192.024 ; U27.40@211.088,156.377 v2(211.088,159.055)
  Top Layer w0.8: TP21.1@203.593,192.024 TP21.1@203.846,192.277 ; TP21.1@203.593,192.53 203.593,195.165 205.175,196.748 R140.2@205.175,200.037
  Bottom Layer w0.3: v2(202.406,162.007) 205.927,162.007 207.557,160.377 209.766,160.377 v2(211.088,159.055)
PWMC: R138.2 TP20.1 U27.48 | length 228
  Top Layer w0.2: v2(188.411,138.05) 188.519,138.05 188.802,138.333 188.835,138.333 189,138.498 189,144.368 189.806,145.174 189.806,157.205 189.947,157.347 189.963,157.347 190.254,157.638 v2(190.363,157.638)
  Top Layer w0.3: U27.48@207.088,156.377 v2(207.088,157.638)
  Top Layer w0.4: v2(190.363,157.638) 190.417,157.638 190.869,158.09 v2(201.092,158.09)
  Top Layer w0.8: v2(59.331,194.627) 59.331,196.625 TP20.1@59.642,196.937 ; R138.2@59.579,200.643 59.61,200.611 TP20.1@59.61,197.373
  Bottom Layer w0.2: v2(59.331,194.627) 59.331,141.919 62.75,138.5 187.425,138.5 187.843,138.083 188.378,138.083 v2(188.411,138.05) ; v2(201.092,158.09) 201.544,157.638 v2(207.088,157.638)
QA_C: D5.2 D8.1 Q2.2 U1.1 U4.5 U4.6 U4.7
  other v1: 115.698,188.4 114.298,189.1 117.098,189.1 114.098,190.7 117.198,190.7 115.698,191.6 88.5,210.63 95.6,210.63 87.1,211.33 89.9,211.33 94.2,211.33 97,211.33 86.9,212.93 90,212.93 94,212.93 97.1,212.93 88.5,213.83 95.6,213.83
QA_GATE: Q2.1 Q3.1 R136.2 R159.1 U23.7 | length 19
  Top Layer w0.8: 119.648,200.078 120.639,201.069 120.892,201.069 121.5,201.677 U23.7@122.501,201.677
  Top Layer w1: 113.698,206.613 113.698,210.358 114.101,210.761 114.101,218.903 Q3.1@115.648,220.45 ; R136.2@116.904,203.407 116.904,203.097 R136.2@117.054,202.947 R136.2@117.054,202.672
QB_C: D6.2 D9.1 Q4.2 U2.1 U5.5 U5.6 U5.7
  other v1: 188.698,188.4 187.298,189.1 190.098,189.1 187.098,190.7 190.198,190.7 188.698,191.6 161.5,210.63 168.6,210.63 160.1,211.33 162.9,211.33 167.2,211.33 170,211.33 159.9,212.93 163,212.93 167,212.93 170.1,212.93 161.5,213.83 168.6,213.83
QB_GATE: Q4.1 Q5.1 R141.2 R161.1 U25.7 | length 18.4
  Top Layer w0.8: 192.648,200.528 193.033,200.528 194.632,202.127 U25.7@195.422,202.127
  Top Layer w1: 186.65,207.061 186.65,218.452 Q5.1@188.648,220.45 ; R141.2@189.889,203.822 189.904,203.822 190.054,203.672 R141.2@190.054,203.122
QC_C: D7.2 D10.1 Q6.2 U3.1 U6.5 U6.6 U6.7
  other v1: 42.698,188.4 41.298,189.1 44.098,189.1 41.098,190.7 44.198,190.7 42.698,191.6 15.5,210.63 22.6,210.63 14.1,211.33 16.9,211.33 21.2,211.33 24,211.33 13.9,212.93 17,212.93 21,212.93 24.1,212.93 15.5,213.83 22.6,213.83
QC_GATE: Q6.1 Q7.1 R139.2 R160.1 U24.7 | length 17.3
  Top Layer w0.8: 46.709,199.588 47.979,200.858 U24.7@49.25,200.858
  Top Layer w1: 40.652,207.196 40.652,210.652 41.4,211.4 41.4,219.155 Q7.1@42.695,220.45 ; Q6.1@46.586,195.512 Q6.1@46.648,195.45
RELAY: R1.2 U27.26 | length 166.4
  Top Layer w0.3: U27.26@214.088,149.877 215.144,149.877 216.167,148.853 216.167,147.622 217.962,145.828 221.402,145.828 221.57,145.66 226.071,145.66 226.815,144.917 226.815,140.844 222.009,136.037 v2(222.009,127.411)
  Top Layer w0.8: R1.2@203.395,33.003 203.468,33.077 v2(203.468,33.996)
  Bottom Layer w0.3: v2(203.468,33.996) 203.468,34.077 204.666,35.275 204.985,35.275 220.335,50.625 241.092,50.625 242.497,52.031 242.497,101.253 222.561,121.189 222.561,126.859 v2(222.009,127.411)
RELAY_DRIVE: D2.2 K1.3 K2.3 Q1.3 | length 64.6
  Top Layer w0.5: K2.3@184.92,26.479 189.151,26.479 v2(189.575,26.902) ; K1.3@197.45,69.06 193.81,69.06 190.04,65.29 190.04,29.739 v2(191.25,28.529) 198.658,28.529 199.25,27.936 200.562,27.936 200.609,27.889 Q1.3@200.609,27.857 ; D2.2@200.347,26.569 D2.2@200.499,26.569
  Top Layer w1: D2.2@200.499,26.569 200.567,26.569 200.609,26.612 Q1.3@200.609,27.857
  Bottom Layer w0.5: v2(189.575,26.902) 191.182,28.509 191.231,28.509 v2(191.25,28.529)
RX: J9.2 R147.2 | length 2
  Top Layer w0.6: J9.2@207.118,179.131 207.319,178.93 207.319,177.683 207.663,177.339 R147.2@207.663,177.314
SYS_RX: R146.1 U27.2 | length 14.8
  Top Layer w0.3: U27.2@205.588,154.377 204.772,154.377 204.162,154.986 204.162,165.549 205.098,166.484 R146.1@206.327,166.484
SYS_TX: R149.1 U27.1 | length 16.9
  Top Layer w0.3: U27.1@205.588,154.877 205.604,154.877 205.604,156.812 204.841,157.574 204.841,162.784 207.227,165.169 210.961,165.169 211.579,165.787 R149.1@211.579,166.479
TMPA: C28.1 R22.1 U27.6 | length 9.9
  Top Layer w0.3: R22.1@196.668,152.752 196.693,152.752 197.693,153.752 199.689,153.752 200.689,152.752 C28.1@200.714,152.752 202.554,152.752 202.929,152.377 U27.6@205.588,152.377
TMPB: C29.1 R23.1 U27.5 | length 9.9
  Top Layer w0.3: R23.1@197.392,155.184 197.417,155.184 198.299,154.302 199.806,154.302 200.724,155.22 C29.1@200.749,155.22 201.711,155.22 204.055,152.877 U27.5@205.588,152.877
TMPC: C30.1 R24.1 U27.14 | length 11.7
  Top Layer w0.3: R24.1@204.772,138.04 204.772,138.065 203.885,138.951 203.885,141.106 204.772,141.993 C30.1@204.772,142.018 204.772,143.427 207.588,146.243 U27.14@207.588,147.877
TX: J9.3 R148.2 | length 1.8
  Top Layer w0.6: J9.3@209.658,179.131 209.675,179.114 209.675,177.331 R148.2@209.691,177.314
V_A: K1.2 L4.1 R80.1 | length 106.7
  Top Layer w0.5: 153.6,79.595 153.6,49.15 160.5,42.25 169.5,42.25 174.136,37.614 174.136,19.978 181.977,12.137 202.42,12.137 203.056,12.772 203.221,12.772 203.606,13.157 R80.1@203.606,13.322
  other v1: 182.291,81.282 180.891,81.782 183.491,81.782 180.42,83.011 183.965,83.03 180.961,84.282 183.491,84.282 182.21,84.811 94.9,98.95 95.75,98.95 96.7,99.015 94.1,99.35 97.5,99.45 93.4,99.95 98.1,100.15 93,100.75 98.5,100.95 92.8,101.65 98.7,101.85 93,102.55 98.5,102.75 93.4,103.35 98.1,103.55 94,104.05 97.4,104.15 94.8,104.485 96.6,104.55 95.7,104.65
V_B: K2.2 L5.1 R91.1 RT1.2 | length 10.9
  Top Layer w0.5: 204.831,41.25 210.818,35.263 R91.1@210.818,32.876
  other v1: 198.971,39.971 197.571,40.471 200.171,40.471 197.1,41.7 200.645,41.719 197.641,42.971 200.171,42.971 198.89,43.5 156.4,98.2 157.25,98.2 158.2,98.265 155.6,98.6 159,98.7 154.9,99.2 159.6,99.4 154.5,100 160,100.2 154.3,100.9 160.2,101.1 154.5,101.8 160,102 154.9,102.6 159.6,102.8 155.5,103.3 158.9,103.4 156.3,103.735 158.1,103.8 157.2,103.9
V_B2: L5.2 U2.2
  other v1: 156.4,162.2 157.25,162.2 158.2,162.265 155.6,162.6 159,162.7 154.9,163.2 159.6,163.4 154.5,164 160,164.2 154.3,164.9 160.2,165.1 154.5,165.8 160,166 154.9,166.6 159.6,166.8 155.5,167.3 158.9,167.4 156.3,167.735 158.1,167.8 157.2,167.9
V_BUSN_AD: C121.2 R130.2 U27.11 | length 11.4
  Top Layer w0.3: R130.2@196.631,147.428 196.656,147.428 197.572,146.512 199.737,146.512 200.652,147.428 C121.2@200.677,147.428 202.406,147.428 202.988,148.01 202.988,149.194 203.671,149.877 U27.11@205.588,149.877
V_BUSP_AD: C112.2 R119.2 U27.9 | length 10.5
  Top Layer w0.3: R119.2@196.679,148.995 196.704,148.995 197.636,149.927 199.72,149.927 200.652,148.995 C112.2@200.677,148.995 201.929,148.995 203.811,150.877 U27.9@205.588,150.877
